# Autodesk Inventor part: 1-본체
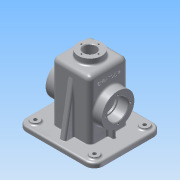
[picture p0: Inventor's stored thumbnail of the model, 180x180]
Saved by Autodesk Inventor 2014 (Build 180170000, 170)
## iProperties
Created: 2015-12
Part Number: 1-본체
Material: 알루미늄 6061
Document SubType Name: Modeling
Designer: Administrator
Density: 2.71 g/cm^3
Appearance: 알루미늄 - 평지
Mass: 804.853 g
Surface Area: 910.469 cm^2
Volume: 296.994 cm^3
Author: Administrator
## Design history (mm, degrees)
sketch "스케치1"
  geometry: L1 (-32.5, -32.5)-(32.5, -32.5); L2 (32.5, -32.5)-(32.5, 32.5); L3 (32.5, 32.5)-(-32.5, 32.5); L4 (-32.5, 32.5)-(-32.5, -32.5); L5 (-32.5, -32.5)-(32.5, 32.5); L6 (32.5, -32.5)-(-32.5, 32.5); 1 further point
  constraints: 12 end point, 2 midpoint, 2 parallel, 1 horizontal, 1 perpendicular
  dimensions: "d0" = 65 distance of L3.end L2.end; "d1" = 65 distance of L2.end L1.end
extrude "돌출1" new body sketch "스케치1" distance "d2" = 100; taper "d3" = 0 deg
feature "쉘1" dims "d4" = 5
sketch "스케치2"
  geometry: C1 r 20 at (0, 0); 1 further point
  constraints: 1 centre point, 1 coincident
  dimensions: "d5" = 40 diameter of C1
extrude "돌출2" join sketch "스케치2" distance "d6" = 10; taper "d7" = 0 deg
sketch "스케치3"
  geometry: L1 (-27.5, 27.5)-(-27.5, -27.5) reference; L2 (-27.5, -27.5)-(27.5, -27.5) reference; L3 (27.5, -27.5)-(27.5, 27.5) reference; L4 (27.5, 27.5)-(-27.5, 27.5) reference; L5 (-32.5, -32.5)-(-32.5, 32.5) reference; L6 (-32.5, 32.5)-(32.5, 32.5) reference; L7 (32.5, 32.5)-(32.5, -32.5) reference; L8 (32.5, -32.5)-(-32.5, -32.5) reference; L9 (65, -57.5)-(-65, -57.5); L10 (-65, -57.5)-(-65, 57.5); L11 (-65, 57.5)-(65, 57.5); L12 (65, 57.5)-(65, -57.5); L13 (65, -57.5)-(-65, 57.5); L14 (-65, -57.5)-(65, 57.5); L15 (27.5, 27.5)-(-27.5, 27.5); L16 (-27.5, 27.5)-(-27.5, -27.5); L17 (-27.5, -27.5)-(27.5, -27.5); L18 (27.5, -27.5)-(27.5, 27.5); 1 further point
  constraints: 20 end point, 4 parallel, 2 horizontal, 2 midpoint, 2 perpendicular
  dimensions: "d8" = 130 distance of L10.end L11.end; "d9" = 115 distance of L9.end L10.end
extrude "돌출3" join sketch "스케치3" distance "d10" = 8; taper "d11" = 0 deg
sketch "스케치4"
  geometry: L1 (-65, -57.5)-(65, -57.5) reference; L2 (65, -57.5)-(65, 57.5) reference; L3 (65, 57.5)-(-65, 57.5) reference; L4 (-65, 57.5)-(-65, -57.5) reference; L5 (-60, 52.5)-(60, 52.5); L6 (60, 52.5)-(60, -52.5); L7 (60, -52.5)-(-60, -52.5); L8 (-60, -52.5)-(-60, 52.5); L9 (-27.5, 27.5)-(27.5, 27.5); L10 (27.5, 27.5)-(27.5, -27.5); L11 (27.5, -27.5)-(-27.5, -27.5); L12 (-27.5, -27.5)-(-27.5, 27.5); 1 further point
  constraints: 16 end point, 2 parallel, 1 horizontal, 1 perpendicular, 3 other
  dimensions: "d12" = 5 distance between parallel lines of L3 L5
extrude "돌출4" join sketch "스케치4" distance "d13" = 2; taper "d14" = 0 deg
sketch "스케치5"
  geometry: L1 (-110, -20)-(-110, 85) reference; L2 (-100, -25)-(-100, 90) reference; C1 r 27.5 at (-55, 32.5); 2 further points
  constraints: 1 centre point, 1 horizontal alignment, 1 midpoint
  dimensions: "d15" = 55 diameter of C1; "d16" = 55 distance from line of C1.centre L1
extrude "돌출5" join sketch "스케치5" distance "d17" = 15; taper "d18" = 0 deg
sketch "스케치6"
  geometry: L1 (32.5, -32.5)-(32.5, 32.5) reference; L2 (-32.5, -32.5)-(32.5, -32.5) reference; L3 (32.5, 3)-(42.5, 3); L4 (42.5, 3)-(42.5, -3); L5 (42.5, -3)-(32.5, -3); L6 (32.5, 3)-(32.5, -3); L7 (27.5, -27.5)-(27.5, 27.5) reference; 2 further points
  constraints: 8 end point, 3 perpendicular, 2 point on line, 1 horizontal alignment, 1 midpoint, 1 parallel
  dimensions: "d19" = 6 distance of L3.end L4.end; "d20" = 15 distance between parallel lines of L4 L7
extrude "돌출6" join sketch "스케치6" stored distance "d21" = 15; taper "d22" = 0 deg
sketch "스케치7"
  geometry: L1 (20, 110)-(20, 100) reference; L2 (20, 100)-(32.5, 100) reference; L3 (32.5, 100)-(32.5, 0) reference; L4 (32.5, 0)-(57.5, 0) reference; L5 (57.5, 0)-(57.5, -8) reference; L6 (57.5, -8)-(52.5, -8) reference; L7 (52.5, -8)-(52.5, -10) reference; L8 (52.5, -10)-(27.5, -10) reference; L9 (27.5, -10)-(27.5, 95) reference; L10 (27.5, 95)-(-27.5, 95) reference; L11 (-27.5, 95)-(-27.5, -10) reference; L12 (-27.5, -10)-(-52.5, -10) reference; L13 (-52.5, -10)-(-52.5, -8) reference; L14 (-52.5, -8)-(-57.5, -8) reference; L15 (-57.5, -8)-(-57.5, 0) reference; L16 (-57.5, 0)-(-32.5, 0) reference; L17 (-32.5, 0)-(-32.5, 100) reference; L18 (-32.5, 100)-(-20, 100) reference; L19 (-20, 100)-(-20, 110) reference; L20 (-20, 110)-(20, 110) reference; L21 (47.5, 0)-(32.5, 85.069); 1 further point
  constraints: 2 end point, 2 point on line
  dimensions: "d23" = 10 distance of L4.end L21.start; "d24" = 100 deg angle of L4 L21
feature "리브1" sketch "스케치7" dims "d25" = 1, "d26" = 10, "d27" = 0, "d28" = 0, "d29" = 1, "d30" = 1
fillet "모깎기1" dims "d31" = 15
sketch "스케치8"
  geometry: C1 r 7.5 at (-50, 42.5); C2 r 7.5 at (50, 42.5); C3 r 7.5 at (50, -42.5); C4 r 7.5 at (-50, -42.5); A1 r 15 centre (50, -42.5) between (50, -57.5) and (65, -42.5) reference; A2 r 15 centre (50, 42.5) between (65, 42.5) and (50, 57.5) reference; A3 r 15 centre (-50, 42.5) between (-50, 57.5) and (-65, 42.5) reference; A4 r 15 centre (-50, -42.5) between (-65, -42.5) and (-50, -57.5) reference; 1 further point
  constraints: 4 centre point, 4 coincident, 3 equal radius
  dimensions: "d32" = 15 diameter of C1
extrude "돌출7" join sketch "스케치8" distance "d33" = 3; taper "d34" = 0 deg
sketch "스케치9"
  geometry: C1 r 7.5 at (0, 0) reference; C2 r 3 at (0, 0); 1 further point
  constraints: 1 centre point, 1 coincident
  dimensions: "d35" = 6 diameter of C2
extrude "돌출8" cut sketch "스케치9" distance "d36" = 20; taper "d37" = 0 deg
fillet "모깎기2" dims "d44" = 10
sketch "스케치10"
  geometry: C1 r 27.5 at (0, 0) reference; C2 r 17.5 at (0, 0); 1 further point
  constraints: 1 centre point, 1 coincident
  dimensions: "d45" = 35 diameter of C2
extrude "돌출9" cut sketch "스케치10" distance "d46" = 17; taper "d47" = 0 deg
sketch "스케치11"
  geometry: C1 r 17.5 at (0, 0) reference; C2 r 15 at (0, 0); 1 further point
  constraints: 1 centre point, 1 coincident
  dimensions: "d48" = 30 diameter of C2
extrude "돌출10" cut sketch "스케치11" stored distance "d49" = 0; taper "d50" = 0 deg
sketch "스케치12" dims "d51" = 42
  geometry: C1 r 17.5 at (0, 0) reference; C2 r 27.5 at (0, 0) reference; 3 further points
  constraints: 2 horizontal alignment, 1 coincident, 2 other
hole "구멍1" sketch "스케치12" at (-21, 0) diameter "d52" = 3.242; stored, may be unused: countersink angle "d56" = 90 deg, drill point angle "d58" = 118 deg; dims "d53" = 8, "d54" = 4, "d55" = 2, "d57" = 10
sketch "스케치13"
  geometry: C1 r 20 at (0, 0) reference; C2 r 10.5 at (0, 0)
  constraints: 1 centre point, 1 coincident
  dimensions: "d62" = 21 diameter of C2
extrude "돌출11" cut sketch "스케치13" stored distance "d63" = 0; taper "d64" = 0 deg
sketch "스케치14" dims "d65" = 29
  geometry: C1 r 10.5 at (0, 0) reference; C2 r 20 at (0, 0) reference; 2 further points
  constraints: 2 vertical alignment, 1 coincident, 2 other
hole "구멍2" sketch "스케치14" at (0, 14.5) diameter "d66" = 2.459; stored, may be unused: countersink angle "d70" = 90 deg, drill point angle "d72" = 118 deg; dims "d67" = 7, "d68" = 4, "d69" = 2, "d71" = 9
fillet "모깎기3" dims "d76" = 8
fillet "모깎기4" dims "d77" = 8
chamfer "모따기1" distance "d78" = 1; stored, may be unused: second distance "d79" = 2, angle "d80" = 45 deg
fillet "모깎기5" dims "d81" = 3
fillet "모깎기6" dims "d82" = 3
fillet "모깎기7" dims "d83" = 3
fillet "모깎기8" dims "d84" = 3
fillet "모깎기9" dims "d85" = 3
fillet "모깎기10" dims "d86" = 3
fillet "모깎기11" dims "d87" = 3
fillet "모깎기12" dims "d88" = 1
fillet "모깎기13" dims "d89" = 3
fillet "모깎기14" dims "d90" = 3
fillet "모깎기15" dims "d91" = 3
sketch "스케치15"
  geometry: L1 (0, -8)-(91, -8) reference; L2 (-18, 44.5)-(-18, 4.5) reference; 2 further points
  constraints: 1 other
  dimensions: "d92" = 32.5 distance from line of point (8, 24.5) L1; "d93" = 26 distance from line of L2 point (8, 24.5)
feature "엠보싱1" sketch "스케치15" dims "d94" = 0.5, "d95" = 0
fillet "모깎기16" dims "d96" = 0.3
node "솔리드1"
mirror "대칭1"
mirror "대칭2"
mirror "대칭3"
pattern_linear "직사각형 패턴1" dims "d40" = 100, "d43" = 85
mirror "대칭4"
pattern_circular "원형 패턴1" dims angle "d60" = 360 deg
mirror "대칭5"
pattern_circular "원형 패턴2" dims angle "d74" = 360 deg
node "작업 평면1"
node "절단 모서리 투영1"
node "절단 모서리 투영2"
